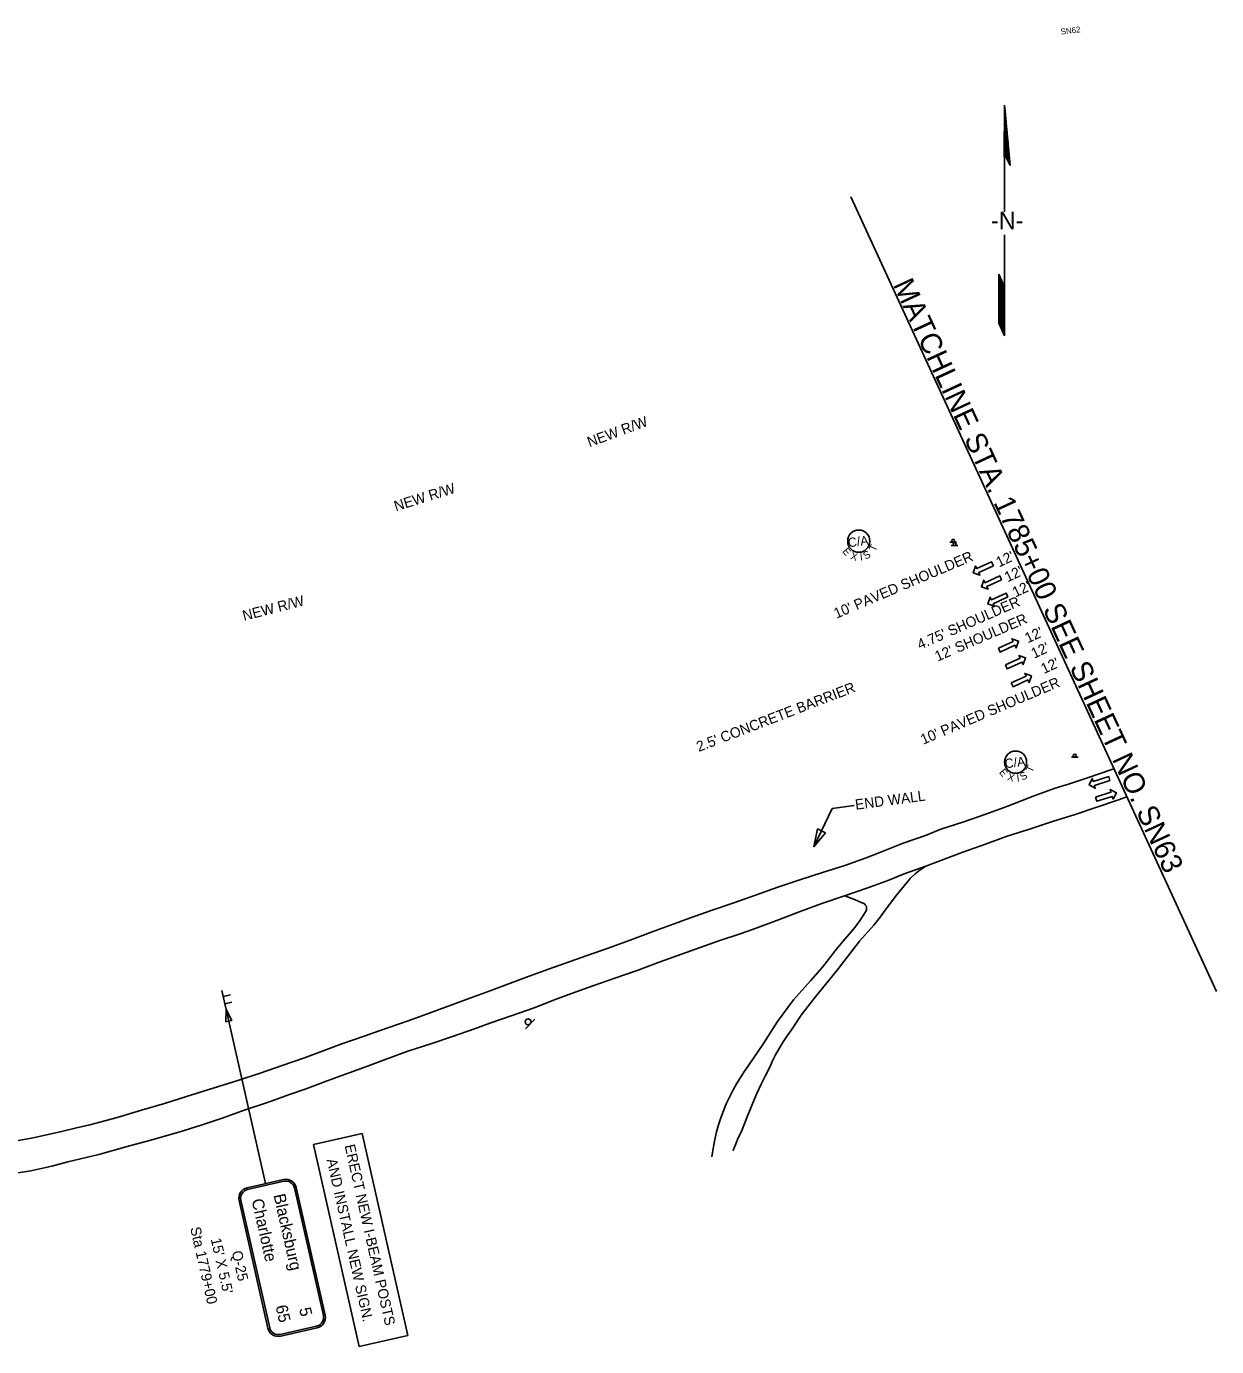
# Model space of a CAD drawing. Extents: x 1823450 to 1825059, y 1192489 to 1193580.
# Drawn here: x 1824254 to 1825059, y 1192688 to 1193580 of the extents above; entities that cross this region are included whole.
import ezdxf

# ---------------------------------------------------------------- set-up
doc = ezdxf.new("R2010")
doc.units = 0
for name, color, linetype in [('RD_EX_BldgApp', 7, 'Continuous'), ('RD_EX_Road', 7, 'Continuous'), ('RD_PD_Final_LnLine', 7, 'Continuous'), ('RD_PD_Final_TX', 7, 'Continuous'), ('RD_PD_RW_TX', 7, 'Continuous'), ('RD_SHT_MatchLine', 7, 'Continuous'), ('RD_SHT_TX', 7, 'Continuous'), ('RD_Sketch1', 7, 'Continuous'), ('RD_Sketch8', 7, 'Continuous'), ('SN_P_Signs', 7, 'Continuous'), ('TERMINATOR', 7, 'Continuous')]:
    doc.layers.add(name, color=color, linetype=linetype)

# ---------------------------------------------------------------- blocks, each defined once
blk = doc.blocks.new('SARRW2')
at = {"layer": 'RD_PD_Final_LnLine'}
blk.add_lwpolyline([(-12, 1.2), (-12, -1.2), (-2.83, -1.2), (-2.83, -2.83), (0, 0), (-2.83, 2.83), (-2.83, 1.2)], close=True, dxfattribs=at)

msp = doc.modelspace()

# ---------------------------------------------------------------- linework, layer by layer
at = {"layer": 'RD_EX_BldgApp'}
for p, q in [((1824878.67, 1193231.59), (1824883.17, 1193231.59)), ((1824879.63, 1193229.35), (1824884.13, 1193229.35)), ((1824960.91, 1193086.35), (1824965.41, 1193086.35)), ((1824591.78, 1192902.67), (1824598.14, 1192909.04))]:
    msp.add_line(p, q, dxfattribs=at)
for centre, radius in [((1824880.93, 1193232.6), 1), ((1824881.89, 1193230.36), 1), ((1824963.17, 1193087.37), 1), ((1824593.54, 1192907.3), 2)]:
    msp.add_circle(centre, radius, dxfattribs=at)
at = {"layer": 'RD_EX_Road'}
for points in [[(1824989.79, 1193078.32), (1824987.63, 1193077.67), (1824972.39, 1193072.56), (1824957.66, 1193067.66), (1824957.41, 1193067.59), (1824949.87, 1193065.24), (1824942.39, 1193062.7), (1824934.98, 1193059.97), (1824927.64, 1193057.07), (1824917.23, 1193052.86), (1824902.25, 1193047.47), (1824887.55, 1193042.42), (1824872.61, 1193037.5), (1824862.13, 1193033.41), (1824847.17, 1193028.07), (1824832.42, 1193022.34), (1824822.22, 1193018.34), (1824807.6, 1193012.97), (1824792.59, 1193008.21), (1824777.3, 1193003.31), (1824762.34, 1192998.37), (1824747.21, 1192993.09), (1824732.63, 1192987.84), (1824717.31, 1192982.67), (1824702.69, 1192977.44), (1824692.35, 1192973.52), (1824677.52, 1192968.14), (1824662.54, 1192962.48), (1824647.67, 1192957.22), (1824632.82, 1192951.93), (1824607.39, 1192942.93), (1824592.57, 1192937.55), (1824567.15, 1192928.14), (1824552.34, 1192922.61), (1824537.62, 1192917.33), (1824527.34, 1192913.47), (1824512.39, 1192908.11), (1824492.94, 1192901.19), (1824482.69, 1192897.69), (1824467.57, 1192892.51), (1824442.36, 1192883.08), (1824427.24, 1192877.84), (1824412.3, 1192872.68), (1824397.27, 1192867.77), (1824377.8, 1192861.63), (1824362.65, 1192856.76), (1824347.64, 1192852.18), (1824332.27, 1192847.49), (1824317.34, 1192843.03), (1824307.29, 1192840.39), (1824297.24, 1192837.75), (1824287.24, 1192835.37), (1824277.24, 1192832.98), (1824257.75, 1192828.74), (1824247.58, 1192826.84)], [(1824242.73, 1192804.3), (1824257.25, 1192806.65), (1824271.61, 1192809.78), (1824282.47, 1192812.7), (1824303.33, 1192817.7), (1824322.38, 1192823), (1824337.58, 1192827.19), (1824357.49, 1192832.71), (1824372.55, 1192837.55), (1824387.47, 1192842.51), (1824402.35, 1192847.84), (1824417.42, 1192852.77), (1824432.31, 1192858.19), (1824442.79, 1192861.8), (1824457.71, 1192867.33), (1824472.5, 1192872.9), (1824483.15, 1192876.66), (1824497.5, 1192882.14), (1824512.21, 1192887.39), (1824527.73, 1192892.44), (1824542.43, 1192897.47), (1824557.4, 1192902.68), (1824567.7, 1192906.45), (1824582.77, 1192911.51), (1824597.68, 1192916.89), (1824612.47, 1192922.55), (1824622.82, 1192926.39), (1824637.99, 1192931.84), (1824652.25, 1192936.94), (1824667.31, 1192942.14), (1824682.26, 1192947.68), (1824697.29, 1192953.01), (1824722.6, 1192962.03), (1824737.62, 1192967.01), (1824747.77, 1192970.69), (1824762.89, 1192976.41), (1824777.5, 1192981.87), (1824792.2, 1192987.28), (1824807.57, 1192992.47), (1824822.56, 1192997.76), (1824837.33, 1193003.05), (1824847.86, 1193007.32), (1824862.35, 1193012.52), (1824887.51, 1193021.96), (1824902.85, 1193027.53), (1824917.38, 1193032.84), (1824932.47, 1193037.67), (1824948.7, 1193042.94), (1824962.74, 1193047.33), (1824992.66, 1193057.41), (1824998.45, 1193059.5)], [(1824862.35, 1193012.52), (1824858.72, 1193010.13), (1824855.33, 1193007.42), (1824852.19, 1193004.41), (1824849.84, 1193001.75), (1824842.53, 1192993.04), (1824834.93, 1192982.85), (1824831.54, 1192978.21), (1824827.39, 1192972.7)], [(1824818.15, 1192976.16), (1824822.11, 1192982.3), (1824822.38, 1192983.14), (1824822.45, 1192984.02), (1824822.34, 1192984.89), (1824822.03, 1192985.72), (1824821.54, 1192986.45), (1824820.91, 1192987.06), (1824820.15, 1192987.51), (1824819.96, 1192987.59), (1824813.14, 1192990.54), (1824807.58, 1192992.46)], [(1824717.78, 1192816.02), (1824717.98, 1192817.71), (1824718.79, 1192822.81), (1824719.79, 1192827.87), (1824720.99, 1192832.89), (1824722.31, 1192837.64), (1824723.88, 1192842.45), (1824725.64, 1192847.2), (1824727.57, 1192851.87), (1824729.69, 1192856.47), (1824731.99, 1192860.98), (1824734.46, 1192865.4), (1824737.11, 1192869.72), (1824739.91, 1192873.93), (1824742.17, 1192877.08), (1824752.59, 1192892.73), (1824762.16, 1192907.45), (1824772.99, 1192922.14), (1824784.4, 1192935), (1824792.5, 1192944.3), (1824802.72, 1192957.27), (1824814.44, 1192971.13), (1824818.15, 1192976.16)], [(1824827.39, 1192972.7), (1824817.64, 1192961.84), (1824802.42, 1192942.38), (1824787.74, 1192924.01), (1824778.14, 1192911.79), (1824771.59, 1192902.01), (1824768.67, 1192897.91), (1824765.91, 1192893.7), (1824763.32, 1192889.38), (1824760.89, 1192884.96), (1824758.65, 1192880.45), (1824757.12, 1192877.11), (1824754, 1192871.14), (1824751.05, 1192865.09), (1824748.29, 1192858.95), (1824747.82, 1192857.86), (1824741.55, 1192843.2), (1824737.51, 1192832.77), (1824735.61, 1192828.89), (1824733.89, 1192824.93), (1824732.35, 1192820.89), (1824732.12, 1192820.18)]]:
    msp.add_lwpolyline(points, dxfattribs=at)
at = {"layer": 'RD_PD_Final_TX'}
for p, q in [((1824799.23, 1193051.64), (1824786.75, 1193025.71)), ((1824813.99, 1193053.6), (1824799.23, 1193051.64))]:
    msp.add_line(p, q, dxfattribs=at)
at = {"layer": 'RD_SHT_MatchLine'}
msp.add_line((1824811.8, 1193465.16), (1825059.04, 1192927.81), dxfattribs=at)
at = {"layer": 'RD_Sketch1'}
for p, q in [((1824915.73, 1193527.19), (1824915.52, 1193492.02)), ((1824919.45, 1193486.49), (1824915.73, 1193527.19)), ((1824915.73, 1193492.32), (1824915.73, 1193470.5)), ((1824916.03, 1193493.43), (1824919.45, 1193486.49)), ((1824915.73, 1193470.5), (1824915.73, 1193455.02)), ((1824915.73, 1193439.58), (1824915.73, 1193413.8)), ((1824911.73, 1193398.75), (1824911.73, 1193412.92)), ((1824911.73, 1193412.92), (1824915.73, 1193404.36)), ((1824915.73, 1193413.8), (1824915.73, 1193371.28)), ((1824911.73, 1193379.85), (1824911.73, 1193398.75)), ((1824915.73, 1193371.28), (1824911.73, 1193379.85))]:
    msp.add_line(p, q, dxfattribs=at)
for points in [[(1824915.74, 1193492.63), (1824915.74, 1193527.07)], [(1824915.83, 1193492.89), (1824915.83, 1193526.04)], [(1824915.93, 1193493.15), (1824915.93, 1193525)], [(1824916.02, 1193493.41), (1824916.02, 1193523.97)], [(1824916.12, 1193493.25), (1824916.12, 1193522.94)], [(1824916.21, 1193493.06), (1824916.21, 1193521.91)], [(1824916.31, 1193492.87), (1824916.31, 1193520.87)], [(1824916.4, 1193492.68), (1824916.4, 1193519.84)], [(1824915.64, 1193492.37), (1824915.64, 1193513.15)], [(1824916.49, 1193492.49), (1824916.49, 1193518.81)], [(1824916.59, 1193492.3), (1824916.59, 1193517.78)], [(1824916.68, 1193492.1), (1824916.68, 1193516.74)], [(1824916.78, 1193491.91), (1824916.78, 1193515.71)], [(1824916.87, 1193491.72), (1824916.87, 1193514.68)], [(1824916.97, 1193491.53), (1824916.97, 1193513.65)], [(1824917.06, 1193491.34), (1824917.06, 1193512.61)], [(1824917.16, 1193491.15), (1824917.16, 1193511.58)], [(1824917.25, 1193490.95), (1824917.25, 1193510.55)], [(1824917.34, 1193490.76), (1824917.34, 1193509.52)], [(1824917.44, 1193490.57), (1824917.44, 1193508.48)], [(1824917.53, 1193490.38), (1824917.53, 1193507.45)], [(1824917.63, 1193490.19), (1824917.63, 1193506.42)], [(1824917.72, 1193490), (1824917.72, 1193505.39)], [(1824917.82, 1193489.8), (1824917.82, 1193504.35)], [(1824917.91, 1193489.61), (1824917.91, 1193503.32)], [(1824918.01, 1193489.42), (1824918.01, 1193502.29)], [(1824918.1, 1193489.23), (1824918.1, 1193501.26)], [(1824915.55, 1193492.11), (1824915.55, 1193497.25)], [(1824918.2, 1193489.04), (1824918.2, 1193500.22)], [(1824918.29, 1193488.85), (1824918.29, 1193499.19)], [(1824918.38, 1193488.65), (1824918.38, 1193498.16)], [(1824918.48, 1193488.46), (1824918.48, 1193497.13)], [(1824918.57, 1193488.27), (1824918.57, 1193496.09)], [(1824918.67, 1193488.08), (1824918.67, 1193495.06)], [(1824918.76, 1193487.89), (1824918.76, 1193494.03)], [(1824918.86, 1193487.7), (1824918.86, 1193493)], [(1824918.95, 1193487.5), (1824918.95, 1193491.96)], [(1824919.05, 1193487.31), (1824919.05, 1193490.93)], [(1824919.14, 1193487.12), (1824919.14, 1193489.9)], [(1824919.23, 1193486.93), (1824919.23, 1193488.87)], [(1824919.33, 1193486.74), (1824919.33, 1193487.83)], [(1824919.42, 1193486.54), (1824919.42, 1193486.8)], [(1824911.81, 1193379.68), (1824911.81, 1193412.75)], [(1824911.91, 1193379.48), (1824911.91, 1193412.55)], [(1824912, 1193379.28), (1824912, 1193412.35)], [(1824912.09, 1193379.07), (1824912.09, 1193412.15)], [(1824912.19, 1193378.87), (1824912.19, 1193411.94)], [(1824912.28, 1193378.67), (1824912.28, 1193411.74)], [(1824912.38, 1193378.47), (1824912.38, 1193411.54)], [(1824912.47, 1193378.26), (1824912.47, 1193411.34)], [(1824912.57, 1193378.06), (1824912.57, 1193411.13)], [(1824912.66, 1193377.86), (1824912.66, 1193410.93)], [(1824912.76, 1193377.66), (1824912.76, 1193410.73)], [(1824912.85, 1193377.45), (1824912.85, 1193410.52)], [(1824912.94, 1193377.25), (1824912.94, 1193410.32)], [(1824913.04, 1193377.05), (1824913.04, 1193410.12)], [(1824913.13, 1193376.85), (1824913.13, 1193409.92)], [(1824913.23, 1193376.64), (1824913.23, 1193409.71)], [(1824913.32, 1193376.44), (1824913.32, 1193409.51)], [(1824913.42, 1193376.24), (1824913.42, 1193409.31)], [(1824913.51, 1193376.04), (1824913.51, 1193409.11)], [(1824913.61, 1193375.83), (1824913.61, 1193408.9)], [(1824913.7, 1193375.63), (1824913.7, 1193408.7)], [(1824913.8, 1193375.43), (1824913.8, 1193408.5)], [(1824913.89, 1193375.22), (1824913.89, 1193408.3)], [(1824913.98, 1193375.02), (1824913.98, 1193408.09)], [(1824914.08, 1193374.82), (1824914.08, 1193407.89)], [(1824914.17, 1193374.62), (1824914.17, 1193407.69)], [(1824914.27, 1193374.41), (1824914.27, 1193407.49)], [(1824914.36, 1193374.21), (1824914.36, 1193407.28)], [(1824914.46, 1193374.01), (1824914.46, 1193407.08)], [(1824914.55, 1193373.81), (1824914.55, 1193406.88)], [(1824914.65, 1193373.6), (1824914.65, 1193406.67)], [(1824914.74, 1193373.4), (1824914.74, 1193406.47)], [(1824914.83, 1193373.2), (1824914.83, 1193406.27)], [(1824914.93, 1193373), (1824914.93, 1193406.07)], [(1824915.02, 1193372.79), (1824915.02, 1193405.86)], [(1824915.12, 1193372.59), (1824915.12, 1193405.66)], [(1824915.21, 1193372.39), (1824915.21, 1193405.46)], [(1824915.31, 1193372.19), (1824915.31, 1193405.26)], [(1824915.4, 1193371.98), (1824915.4, 1193405.05)], [(1824915.5, 1193371.78), (1824915.5, 1193404.85)], [(1824915.59, 1193371.58), (1824915.59, 1193404.65)], [(1824915.68, 1193371.37), (1824915.68, 1193404.45)]]:
    msp.add_lwpolyline(points, dxfattribs=at)
at = {"layer": 'RD_Sketch8'}
for centre in [(1824817.13, 1193232.37), (1824923.12, 1193082.92)]:
    msp.add_circle(centre, 7.5, dxfattribs=at)
at = {"layer": 'SN_P_Signs'}
for p, q in [((1824878.67, 1193231.59), (1824883.17, 1193231.59)), ((1824879.63, 1193229.35), (1824884.13, 1193229.35)), ((1824960.91, 1193086.35), (1824965.41, 1193086.35)), ((1824389.33, 1192915.77), (1824386.47, 1192928.49)), ((1824387.37, 1192924.48), (1824392.24, 1192925.57)), ((1824388.47, 1192919.58), (1824393.34, 1192920.68)), ((1824415.92, 1192797.91), (1824389.33, 1192915.77)), ((1824591.78, 1192902.67), (1824598.14, 1192909.04)), ((1824448.56, 1192824.31), (1824481.35, 1192831.71)), ((1824481.35, 1192831.71), (1824512.16, 1192695.12)), ((1824479.37, 1192687.72), (1824448.56, 1192824.31)), ((1824435.65, 1192794.98), (1824455.12, 1192708.68)), ((1824436.82, 1192795.24), (1824456.29, 1192708.94)), ((1824512.16, 1192695.12), (1824479.37, 1192687.72))]:
    msp.add_line(p, q, dxfattribs=at)
msp.add_lwpolyline([(1824389.14, 1192907.32), (1824389.33, 1192915.77), (1824393.14, 1192908.22)], close=True, dxfattribs=at)
for points in [[(1824403.63, 1192795.14), (1824428.21, 1192800.68)], [(1824403.89, 1192793.97), (1824428.48, 1192799.51)], [(1824417.66, 1192700.23), (1824398.19, 1192786.53)], [(1824418.83, 1192700.49), (1824399.36, 1192786.79)], [(1824450.59, 1192701.5), (1824426, 1192695.96)], [(1824450.85, 1192700.33), (1824426.27, 1192694.79)]]:
    msp.add_lwpolyline(points, dxfattribs=at)
for centre, radius in [((1824880.93, 1193232.6), 1), ((1824881.89, 1193230.36), 1), ((1824963.17, 1193087.37), 1), ((1824593.54, 1192907.3), 2)]:
    msp.add_circle(centre, radius, dxfattribs=at)
for centre, radius, start, end in [((1824429.8, 1192793.66), 7.2, 12.71215, 102.71215), ((1824429.8, 1192793.66), 6, 12.71215, 102.71215), ((1824405.21, 1192788.11), 7.2, 102.71215, 192.71215), ((1824405.21, 1192788.11), 6, 102.71215, 192.71215), ((1824449.27, 1192707.36), 6, 282.71215, 12.71215), ((1824449.27, 1192707.36), 7.2, 282.71215, 12.71215), ((1824424.68, 1192701.81), 7.2, 192.71215, 282.71215), ((1824424.68, 1192701.81), 6, 192.71215, 282.71215)]:
    msp.add_arc(centre, radius, start, end, dxfattribs=at)
at = {"layer": 'TERMINATOR'}
msp.add_lwpolyline([(1824794.66, 1193035.22), (1824786.75, 1193025.71), (1824789.25, 1193037.83)], close=True, dxfattribs=at)

# ---------------------------------------------------------------- block references
at = {"layer": 'RD_PD_Final_LnLine'}
for p, xscale, yscale, rotation in [((1824894.49, 1193211.03), 1.200000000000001, 1.200000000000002, -155.1613749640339), ((1824899.98, 1193201.5), 1.200000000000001, 1.200000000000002, -155.1613749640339), ((1824904.33, 1193189.89), 1.200000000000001, 1.200000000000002, -155.1613749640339), ((1824925.16, 1193164.67), 1.200000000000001, 1.2000000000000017, 24.838625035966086), ((1824929.9, 1193153.38), 1.200000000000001, 1.2000000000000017, 24.838625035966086), ((1824933.87, 1193141.26), 1.200000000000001, 1.2000000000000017, 24.838625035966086), ((1824972.79, 1193067.57), 1.200000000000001, 1.2000000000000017, -162.73084531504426), ((1824991.28, 1193062.19), 1.2000000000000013, 1.2000000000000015, 17.269154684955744)]:
    msp.add_blockref('SARRW2', p, dxfattribs=dict(at, xscale=xscale, yscale=yscale, rotation=rotation))

# ---------------------------------------------------------------- texts
at = {"layer": 'RD_PD_Final_TX'}
for s, rotation, p in [("10' PAVED SHOULDER", 23.05984, (1824802.04, 1193179.88)), ("12'", 25.17998, (1824911.94, 1193214.53)), ("12'", 25.17998, (1824917.66, 1193204.44)), ("12'", 25.17998, (1824923.01, 1193194.21)), ("4.75' SHOULDER", 23.73134, (1824858.47, 1193158.9)), ("12' SHOULDER", 23.34589, (1824870.37, 1193150.87)), ("12'", 25.17998, (1824931.42, 1193163.19)), ("12'", 25.17998, (1824935.62, 1193152.79)), ("12'", 25.17998, (1824942.29, 1193142.43)), ("2.5' CONCRETE BARRIER", 21.03132, (1824708.93, 1193089.8)), ("10' PAVED SHOULDER", 23.05984, (1824860.68, 1193094.66)), ('END WALL', 7.56198, (1824815.11, 1193050.7))]:
    msp.add_text(s, height=7, rotation=rotation, dxfattribs=at).set_placement(p)
at = {"layer": 'RD_PD_RW_TX'}
for rotation, p in [(20.19094, (1824635.06, 1193295.82)), (17.21806, (1824504.16, 1193252.52)), (14.418, (1824401.46, 1193178.42))]:
    msp.add_text('NEW R/W', height=7, rotation=rotation, dxfattribs=at).set_placement(p)
at = {"layer": 'RD_SHT_TX'}
for s, height, rotation, p in [('SN62', 4, 7.31198, (1824953.91, 1193574.83)), ('MATCHLINE STA. 1785+00 SEE SHEET NO. SN63', 14.1726, 294.77055, (1824840.03, 1193405.9))]:
    msp.add_text(s, height=height, rotation=rotation, dxfattribs=at).set_placement(p)
at = {"layer": 'RD_Sketch1'}
msp.add_text('-N-', height=11.811, rotation=0, dxfattribs=at).set_placement((1824906.53, 1193443.29))
at = {"layer": 'RD_Sketch8'}
for s, height, rotation, p in [('C/A', 6.25, 7.31198, (1824810.19, 1193228.17)), ('E', 5, 310.52322, (1824805.71, 1193225.34)), ('X', 5, 342.9526, (1824811.17, 1193220.34)), ('S', 5, 29.10442, (1824821.76, 1193219.78)), ('T', 5, 65.49713, (1824828.34, 1193225.03)), ('I', 5, 7.1126, (1824818.16, 1193219.15)), ('C/A', 6.25, 7.31198, (1824916.19, 1193078.72)), ('E', 5, 310.52322, (1824911.7, 1193075.89)), ('X', 5, 342.9526, (1824917.16, 1193070.89)), ('I', 5, 7.1126, (1824924.16, 1193069.7)), ('S', 5, 29.10442, (1824927.76, 1193070.33)), ('T', 5, 65.49713, (1824934.34, 1193075.58))]:
    msp.add_text(s, height=height, rotation=rotation, dxfattribs=at).set_placement(p)
at = {"layer": 'SN_P_Signs'}
for s, height, rotation, p in [('ERECT NEW I-BEAM POSTS', 6.9998, 282.71224, (1824469.47, 1192823.66)), ('AND INSTALL NEW SIGN.', 6.9998, 282.71224, (1824457.28, 1192814.05)), ('Charlotte', 8, 282.71215, (1824406.53, 1192786.81)), ('Blacksburg', 8, 282.71215, (1824421.36, 1192790.15)), ('Sta 1779+00', 7, 282.71224, (1824365.06, 1192767.89)), ("15' X 5.5'", 7, 282.71224, (1824378.95, 1192760.4)), ('Q-25', 7, 282.71224, (1824393.09, 1192751.78)), ('65', 8, 282.71215, (1824422.74, 1192714.98)), ('5', 8, 282.71215, (1824438.7, 1192713.29))]:
    msp.add_text(s, height=height, rotation=rotation, dxfattribs=at).set_placement(p)

doc.saveas('drawing.dxf')
